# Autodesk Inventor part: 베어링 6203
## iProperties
IsCustomPart: 0
Created: 2009-02
Part Number: 베어링 6203
Material: 강, 연강
Description: 깊은 그루브 볼 베어링
Document SubType Name: Modeling
Standard: KS B 2023
Designer: 한국산업디자인학원 [http://gmhk.co.kr]
Standards Organization: KS
Language: ko-KR
Size Designation: 6203 - 17 x 40 x 12
Categories: <MemberInstance><Categories><Category DisplayName="샤프트 부품" InternalName="7f7aeb1f-a693-4053-b835-cee3144e0d98" Mnemonic="SHFT"><Category DisplayName="베어링" Inter
Density: 1 g/cm^3
Author: pww
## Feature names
1. IDS_ARRAYBALL[SIMPL:T] [Circular Pattern]
